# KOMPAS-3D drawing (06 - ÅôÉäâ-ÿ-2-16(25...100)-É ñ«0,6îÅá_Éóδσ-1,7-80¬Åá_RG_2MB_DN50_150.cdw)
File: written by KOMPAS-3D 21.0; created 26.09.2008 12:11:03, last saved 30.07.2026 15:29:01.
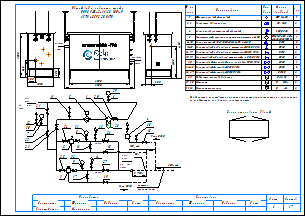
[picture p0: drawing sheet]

Sheets 1-2: A3, landscape

Document properties: Наименование: Макро:21; Автор: RaskoAdmin; Форматы листов документа: 2xA3; Полное имя файла: \\ur38nt01\Departments\КТО\КБ ПУРДГ\Заявки\Прайс-лист на типовые шкафы ГРПШ\ПУРДГ_стандарт_30_04_2026\ПУРДГ с RG_2MB\ПУРДГ-Ш-2-16(25...100)-Р до0,6МПа_Рвых-1,7-80кПа_RG_2MB_DN50_150.cdw

Title block, sheet 1: Наименование: Пункт учета газа / ПУГ-Ш-400-Р / ЛГТИ.485922.001ТУ; designation: ЛГТИ.03.4411141; sheet number: 1; Количество листов документа: 2; organisation: ООО "ЭЛЬСТЕР Газэлектроника"; Форматы листов документа: A3; stored path: C:\Рабочие документы\Компас\ПУГ\Схема.cdw; Разработал: Устинов; Проверил: Кошкин; Утвердил: Кошкин
Title block, sheet 2: sheet number: 2; stored path: D:\Рабочие документы\Заявки\ПУРДГ\ПУРДГ-ШУЭО-2-100-Р 4411220.cdw; designation, second copy: ЛГТИ.03.4411141-

Views: Вид 1, Вид 2
Referenced files: wcvoit.frw
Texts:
  Normal
  № на
  схеме
  Усл.
  обозн.
  Марка
  (модель)
  Кол.
  Фильтр газовый фланцевый
  ФГ 16-50
  Регулятор давления газа
  RG/2MB
  Клапан предохранительный сбросной
  КПС DN20
  Измерительный комплекс с ротационным счетчиком Ду50
  СГ-ЭК-Р-(0,2...2,0)-
  Кран кнопочный VE-РАСКО-НЗ-1,6-G1/2-М20
  DN15
  Кран шаровой "под приварку" штуцерный DN20 PN16
  DN20
  Кран шаровой "под приварку" штуцерный DN15 PN16
  Кран шаровой "под приварку" штуцерный п/п DN20 PN16
  Кран шаровой фланцевый с мех. приводом DN50 PN16
  Кран шаровой фланцевый DN50 PN16
  Кран шаровой фланцевый DN150 PN16
  DN50
  DN150
  Индикатор перепада давления
  Манометр
  Манометр-напоромер
  Delta 15
  0...     МПа
  0...     кПа
  Общий вид и габариты шкафа
  ПУРДГ-Ш-2-16(25...100)-Р
  Выход газа
  Вход газа
  logo-rasko-ge.png
  DN 1
  местное
  сопротивление
  Римп DN20
  Выход
  газа
  Р=     кПа
  Вход
  Р=       МПа
  PDI
  Схема открывания дверей
  Предприятие изготовитель может заменять комплектующие на аналогичные,
  не ухудшающие заявленных характеристик.
  Должность
  Конструктор
  Фамилия
  Подпись
  Дата
  Согласовано
  Максимкин
  Лист
  Листов
  POLYLINE_STYLE_0.18_RGB_0_0_0
  POLYLINE_STYLE_0.50_RGB_0_0_0
  POLYLINE_STYLE_0.34_RGB_0_0_0
  PHANTOM_RGB_0_0_0_SC_1_THICK_0.18
  K5LT_THIN_RGB_0_0_0_THICK_0.18
  K5LT32769_RGB_0_0_0_THICK_0.18
  K5LT12_RGB_0_0_0_SC_1_THICK_0.18
  K5LT_DASHED_RGB_0_0_0_SC_1_THICK_0.18
  ACISOTGL_RGB_0_0_0_SC_0.8_THICK_0.25
  CONTINUOUS_RGB_0_127_31_THICK_0.3
  CONTINUOUS_RGB_0_0_255_THICK_0.35
  CONTINUOUS_RGB_255_0_0_THICK_0.35
  POLYLINE_STYLE_0.25_RGB_0_0_0
  CONTINUOUS_RGB_0_0_0_THICK_0.5
  POLYLINE_STYLE_0.35_RGB_0_0_255
  CONTINUOUS_RGB_0_0_0_THICK_0.4
  CONTINUOUS_RGB_0_0_0_THICK_0.35
  НЕВИДИМАЯ_RGB_0_0_0_SC_0.3_THICK_0.25
  СONTINUOUS_RGB_0_0_0_THICK_0.25
  ОСЕВАЯ2_RGB_248_153_30_SC_0.3_THICK_0.25
  Без оформления
Dimensions and other numbers on the sheet: 1; 2, 3; 2; 4; 5; 6-10; 11-15; 16, 17; 18, 19; 20; 21-25; 26, 27; 28; 29, 30; 31, 32; 1500; 250; 300; 1050; 550; 305; 2500; 4130; 2000; 2800; 5,,,7DN 1; 7; 30; 12; 21; 22; 23; 11; 6; 29; 24; 31; 8; 16; 13; 26; 18; 10; 15; 25; 32; 9; 3; 17; 14; 27; 19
